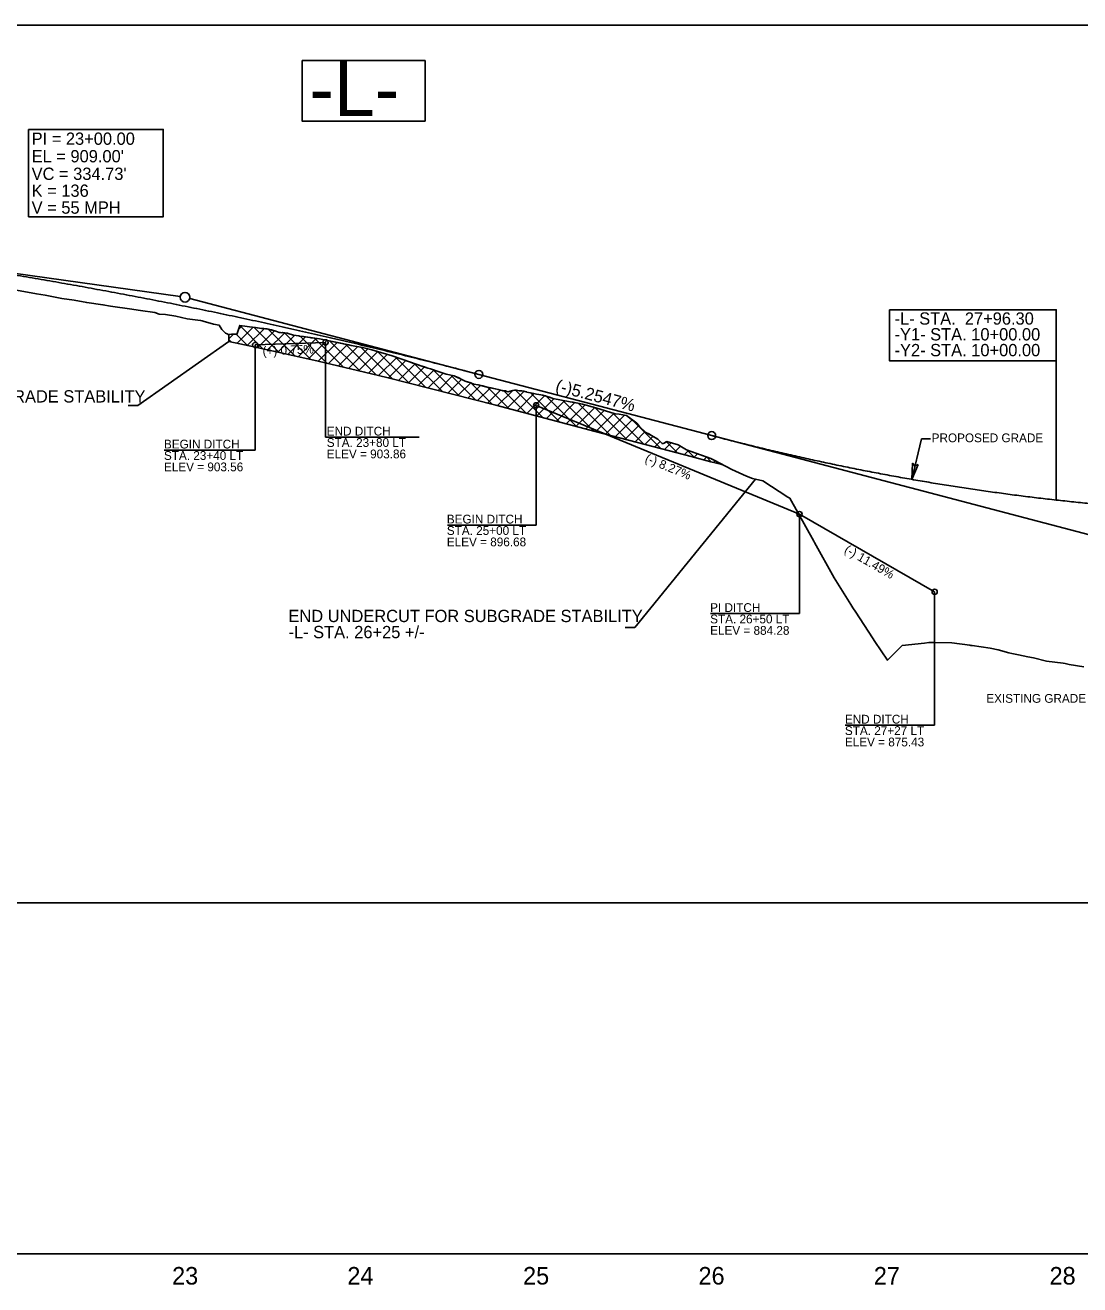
# Model space of a CAD drawing. Extents: x 1968019 to 1983409, y 545058 to 567558.
# Drawn here: x 1970052 to 1970653, y 566291 to 567008 of the extents above; entities that cross this region are included whole.
import ezdxf

# ---------------------------------------------------------------- set-up
doc = ezdxf.new("R2010")
doc.units = 0
for name, color, linetype in [('Exist Profile Cell', 7, 'Continuous'), ('Exist Vertical Profile Ground Line', 7, 'Continuous'), ('Exist Vertical Profile Horizontal Axis Label Major', 7, 'Continuous'), ('Old_Level_1', 7, 'Continuous'), ('Old_Level_20', 7, 'Continuous'), ('Prop Grid Mask', 7, 'Continuous'), ('Prop Road Sect_ Recs - UC (Outline)', 7, 'Continuous'), ('Prop Road Sect_ Recs - UC (pattern)', 7, 'Continuous'), ('Prop Road Sect_ Recs - UC (Tx)', 7, 'Continuous'), ('Prop Terminator CELL', 7, 'Continuous'), ('Prop Vertical Profile Curve Label', 7, 'Continuous'), ('Prop Vertical Profile Ditch Grade Left', 7, 'Continuous'), ('Prop Vertical Profile Ditch Grade Left Label', 7, 'Continuous'), ('Prop Vertical Profile Grade', 7, 'Continuous'), ('Prop Vertical Profile Grade Label', 7, 'Continuous'), ('Prop VPI Label', 7, 'Continuous'), ('Scratch_Level_8', 7, 'Continuous')]:
    doc.layers.add(name, color=color, linetype=linetype)

msp = doc.modelspace()

# ---------------------------------------------------------------- linework, layer by layer
at = {"layer": 'Exist Profile Cell'}
msp.add_line((1968842.96, 566308.43), (1972642.96, 566308.43), dxfattribs=at)
at = {"layer": 'Exist Vertical Profile Ground Line'}
for points in [[(1970046.9, 566857.43), (1970058.36, 566855.38), (1970063.18, 566854.53), (1970072.77, 566852.8), (1970079.73, 566851.7), (1970086.95, 566850.42), (1970096.18, 566849.11), (1970100.53, 566848.37), (1970112.62, 566846.7), (1970113.69, 566846.54), (1970117.65, 566845.93), (1970125.69, 566844.69), (1970128.13, 566843.71), (1970131.76, 566843.64), (1970137.63, 566842.69), (1970144.06, 566841.16), (1970151.84, 566840.25), (1970152.78, 566840.08), (1970153.3, 566839.86), (1970159.08, 566838.12), (1970162.41, 566837.49), (1970163.95, 566835.12), (1970164.65, 566834.38), (1970166.04, 566833.03), (1970166.87, 566832.66), (1970167.53, 566832.27), (1970171.21, 566832.36), (1970172.52, 566832.27), (1970174.12, 566837.33), (1970174.13, 566837.37), (1970185.3, 566835.84), (1970187.86, 566835.53), (1970189.6, 566835.48), (1970194.66, 566834.12), (1970196.65, 566833.37), (1970198.02, 566833.19), (1970198.42, 566833.4), (1970201.17, 566832.99), (1970201.64, 566832.83), (1970204.15, 566831.96), (1970204.71, 566831.8), (1970207.79, 566831.44), (1970208.23, 566831.31), (1970210.51, 566831.01), (1970212.78, 566830.77), (1970214.14, 566830.51), (1970215.57, 566830.25), (1970219.47, 566829.65), (1970229.77, 566827.58), (1970236.26, 566826.27), (1970237.6, 566826), (1970243.97, 566824.79), (1970249.35, 566823.5), (1970253.08, 566822.39), (1970260.86, 566820.11), (1970271.32, 566816.46), (1970274.12, 566815.41), (1970277.28, 566814.44), (1970281.29, 566813.08), (1970282.72, 566812.6), (1970288.2, 566810.69), (1970289.37, 566810.36), (1970291.79, 566809.57), (1970296.28, 566808.61), (1970296.71, 566808.55), (1970301.07, 566806.44), (1970302.56, 566805.58), (1970305.83, 566804.69), (1970307.55, 566803.99), (1970309.96, 566803.52), (1970315.04, 566802.28), (1970319.7, 566801.25), (1970321.41, 566800.86), (1970323.6, 566800.28), (1970323.77, 566800.23), (1970324.05, 566800.14), (1970325.58, 566800.02), (1970326.18, 566799.68), (1970326.88, 566799.51)], [(1970326.88, 566799.51), (1970329.59, 566800.38), (1970331.65, 566800.5), (1970333.31, 566800.12), (1970334.66, 566800.19), (1970337.27, 566799.59), (1970337.47, 566799.52), (1970337.74, 566799.4), (1970341.66, 566798.56), (1970343.1, 566798.3), (1970345.68, 566797.82), (1970347.88, 566797.32), (1970348.27, 566797.23), (1970349.12, 566796.92), (1970351.09, 566796.27), (1970352.45, 566795.72), (1970362.26, 566793.91), (1970365.69, 566793.27), (1970365.81, 566793.25), (1970369.37, 566792.54), (1970376.97, 566790.49), (1970387.99, 566786.97), (1970390.26, 566786.73), (1970394.45, 566786.1), (1970400.22, 566781.6), (1970401.8, 566779.88), (1970405.53, 566776.45), (1970408.7, 566774.59), (1970412.31, 566772.63), (1970412.55, 566772.33), (1970414.74, 566770.02), (1970415.91, 566770.34), (1970417.34, 566771.21), (1970423.89, 566769.35), (1970428.64, 566766.55), (1970442.39, 566761.55), (1970444.39, 566760.56), (1970454.4, 566755.25), (1970462.71, 566751.47), (1970466.27, 566750.2), (1970472.15, 566748.85), (1970486.34, 566739.57), (1970487.46, 566738.88), (1970501.06, 566714.46), (1970501.19, 566714.24), (1970501.34, 566713.99), (1970501.5, 566713.68), (1970512.71, 566693.49), (1970522.19, 566678.39), (1970523.42, 566676.57), (1970525.06, 566674.05), (1970534.5, 566659.39), (1970535.81, 566657.28), (1970543.12, 566646.63), (1970548.01, 566651.56), (1970551.51, 566655.11), (1970564.12, 566656.39), (1970566.66, 566656.7), (1970567.49, 566656.81), (1970568.76, 566656.82), (1970570.35, 566656.76), (1970579.75, 566656.5), (1970590.09, 566655.12), (1970590.66, 566655.05), (1970591.42, 566654.96), (1970601.52, 566653.41), (1970606.18, 566652.49), (1970612.31, 566650.89), (1970613.86, 566650.5), (1970617.81, 566649.69), (1970623.05, 566648.54), (1970626.3, 566647.91), (1970633.73, 566646.1), (1970643.1, 566644.87), (1970644.36, 566644.69), (1970646.66, 566644.27), (1970654.94, 566642.83)]]:
    msp.add_lwpolyline(points, dxfattribs=at)
at = {"layer": 'Old_Level_20'}
for q in [(1970556.88, 566749.68), (1970567.63, 566772.83)]:
    msp.add_line((1970562.46, 566772.83), q, dxfattribs=at)
at = {"layer": 'Prop Grid Mask'}
msp.add_line((1970639.26, 566737.88), (1970639.26, 566817.24), dxfattribs=at)
for points in [[(1970209.57, 566988.31), (1970279.71, 566988.31), (1970279.71, 566953.75), (1970209.57, 566953.75)], [(1970053.84, 566949.03), (1970130.54, 566949.03), (1970130.54, 566899.27), (1970053.84, 566899.27)], [(1970544.18, 566846.26), (1970639.26, 566846.26), (1970639.26, 566817.24), (1970544.18, 566817.24)]]:
    msp.add_lwpolyline(points, close=True, dxfattribs=at)
at = {"layer": 'Prop Road Sect_ Recs - UC (Outline)'}
msp.add_lwpolyline([(1970167.96, 566828.14), (1970183.17, 566824.9), (1970218.74, 566816.98), (1970245.19, 566810.79), (1970257.89, 566807.73), (1970319.96, 566791.92), (1970376.64, 566777.03), (1970414.52, 566767.08), (1970431.3, 566762.67), (1970442.4, 566759.75), (1970448.13, 566758.27), (1970449.27, 566757.97), (1970444.39, 566760.56), (1970443.39, 566761.05), (1970442.39, 566761.55), (1970435.51, 566764.05), (1970428.64, 566766.55), (1970423.89, 566769.35), (1970420.61, 566770.28), (1970417.34, 566771.21), (1970416.62, 566770.77), (1970415.91, 566770.34), (1970415.32, 566770.18), (1970414.74, 566770.02), (1970413.64, 566771.18), (1970412.55, 566772.33), (1970412.31, 566772.63), (1970410.5, 566773.61), (1970408.7, 566774.59), (1970407.11, 566775.52), (1970405.53, 566776.45), (1970401.8, 566779.88), (1970400.22, 566781.6), (1970397.33, 566783.85), (1970394.45, 566786.1), (1970390.26, 566786.73), (1970387.99, 566786.97), (1970376.97, 566790.49), (1970369.37, 566792.54), (1970367.59, 566792.89), (1970365.69, 566793.27), (1970363.97, 566793.59), (1970362.26, 566793.91), (1970357.35, 566794.82), (1970352.45, 566795.72), (1970351.09, 566796.27), (1970348.69, 566797.07), (1970348.27, 566797.23), (1970347.88, 566797.32), (1970346.78, 566797.57), (1970345.68, 566797.82), (1970344.39, 566798.06), (1970343.1, 566798.3), (1970341.66, 566798.56), (1970339.7, 566798.98), (1970337.74, 566799.4), (1970337.6, 566799.46), (1970337.47, 566799.52), (1970337.37, 566799.55), (1970337.27, 566799.59), (1970335.96, 566799.89), (1970334.66, 566800.19), (1970333.31, 566800.12), (1970332.48, 566800.31), (1970331.65, 566800.5), (1970330.62, 566800.44), (1970329.59, 566800.38), (1970328.23, 566799.95), (1970326.88, 566799.51), (1970326.18, 566799.68), (1970325.88, 566799.85), (1970325.58, 566800.02), (1970324.81, 566800.08), (1970324.05, 566800.14), (1970323.91, 566800.19), (1970323.68, 566800.25), (1970322.5, 566800.57), (1970321.41, 566800.86), (1970319.7, 566801.25), (1970317.37, 566801.77), (1970315.04, 566802.28), (1970312.5, 566802.9), (1970309.96, 566803.52), (1970307.55, 566803.99), (1970305.83, 566804.69), (1970304.19, 566805.14), (1970302.56, 566805.58), (1970301.07, 566806.44), (1970298.89, 566807.49), (1970296.71, 566808.55), (1970296.49, 566808.58), (1970296.28, 566808.61), (1970291.79, 566809.57), (1970290.58, 566809.97), (1970289.37, 566810.36), (1970288.2, 566810.69), (1970285.46, 566811.65), (1970282.72, 566812.6), (1970281.29, 566813.08), (1970279.28, 566813.76), (1970277.28, 566814.44), (1970275.7, 566814.92), (1970274.12, 566815.41), (1970272.72, 566815.93), (1970271.32, 566816.46), (1970260.86, 566820.11), (1970249.35, 566823.5), (1970243.97, 566824.79), (1970240.78, 566825.4), (1970237.6, 566826), (1970219.47, 566829.65), (1970217.52, 566829.95), (1970215.57, 566830.25), (1970214.85, 566830.38), (1970214.14, 566830.51), (1970212.78, 566830.77), (1970211.64, 566830.89), (1970210.51, 566831.01), (1970208.23, 566831.31), (1970207.79, 566831.44), (1970206.25, 566831.62), (1970204.71, 566831.8), (1970204.43, 566831.88), (1970204.15, 566831.96), (1970202.89, 566832.4), (1970201.64, 566832.83), (1970201.4, 566832.91), (1970201.17, 566832.99), (1970198.42, 566833.4), (1970198.02, 566833.19), (1970197.33, 566833.28), (1970196.65, 566833.37), (1970195.65, 566833.74), (1970194.66, 566834.12), (1970192.13, 566834.8), (1970189.6, 566835.48), (1970188.73, 566835.5), (1970187.86, 566835.53), (1970186.58, 566835.68), (1970185.3, 566835.84), (1970183.17, 566836.13), (1970179.71, 566836.6), (1970174.13, 566837.37), (1970172.52, 566832.27), (1970171.86, 566832.31), (1970171.21, 566832.36), (1970169.37, 566832.31), (1970167.96, 566832.28)], close=True, dxfattribs=at)
at = {"layer": 'Prop Road Sect_ Recs - UC (pattern)'}
for p, q in [((1970173.42, 566835.14), (1970175.47, 566837.18)), ((1970174.12, 566837.34), (1970187.53, 566823.93)), ((1970167.96, 566829.67), (1970170.63, 566832.34)), ((1970172.09, 566832.3), (1970178.49, 566825.9)), ((1970172.52, 566827.17), (1970181.69, 566836.33)), ((1970178.35, 566825.92), (1970187.95, 566835.52)), ((1970182.27, 566836.25), (1970196.62, 566821.9)), ((1970184.17, 566824.67), (1970193.84, 566834.34)), ((1970189.96, 566823.39), (1970199.77, 566833.2)), ((1970190.3, 566835.29), (1970205.72, 566819.88)), ((1970195.74, 566822.1), (1970205.36, 566831.72)), ((1970199.42, 566833.25), (1970214.81, 566817.85)), ((1970201.52, 566820.81), (1970211.6, 566830.89)), ((1970207.31, 566819.52), (1970217.7, 566829.92)), ((1970208.46, 566831.28), (1970223.99, 566815.75)), ((1970216.74, 566830.07), (1970233.22, 566813.59)), ((1970167.96, 566829.35), (1970169.5, 566827.81)), ((1970213.09, 566818.24), (1970223.66, 566828.8)), ((1970218.87, 566816.95), (1970229.55, 566827.62)), ((1970224.6, 566815.61), (1970235.43, 566826.44)), ((1970225.43, 566828.45), (1970242.45, 566811.43)), ((1970230.33, 566814.27), (1970241.35, 566825.29)), ((1970234.28, 566826.67), (1970251.74, 566809.21)), ((1970236.06, 566812.92), (1970247.16, 566824.03)), ((1970241.79, 566811.58), (1970252.72, 566822.51)), ((1970243.06, 566824.96), (1970261.12, 566806.9)), ((1970252.52, 566822.57), (1970270.6, 566804.49)), ((1970247.51, 566810.23), (1970258.18, 566820.9)), ((1970253.21, 566808.85), (1970263.53, 566819.18)), ((1970258.89, 566807.47), (1970268.77, 566817.35)), ((1970262.69, 566819.47), (1970280.09, 566802.07)), ((1970264.53, 566806.04), (1970273.96, 566815.47)), ((1970273.65, 566815.58), (1970289.58, 566799.66)), ((1970270.16, 566804.6), (1970279.31, 566813.75)), ((1970275.8, 566803.17), (1970284.58, 566811.95)), ((1970281.44, 566801.73), (1970289.9, 566810.19)), ((1970284.24, 566812.07), (1970299.06, 566797.24)), ((1970287.07, 566800.3), (1970295.54, 566808.77)), ((1970294.36, 566809.02), (1970308.55, 566794.83)), ((1970292.71, 566798.86), (1970300.54, 566806.69)), ((1970298.34, 566797.42), (1970305.66, 566804.74)), ((1970303.98, 566795.99), (1970311.21, 566803.22)), ((1970305.73, 566804.72), (1970318.04, 566792.41)), ((1970309.62, 566794.55), (1970316.93, 566801.86)), ((1970315.29, 566802.23), (1970327.61, 566789.91)), ((1970315.25, 566793.12), (1970322.66, 566800.52)), ((1970320.88, 566791.68), (1970329.58, 566800.38)), ((1970324.48, 566800.11), (1970337.2, 566787.39)), ((1970326.48, 566790.21), (1970336.12, 566799.85)), ((1970331.19, 566800.47), (1970346.79, 566784.87)), ((1970332.08, 566788.74), (1970341.87, 566798.52)), ((1970337.68, 566787.27), (1970347.76, 566797.34)), ((1970339.77, 566798.96), (1970356.38, 566782.35)), ((1970343.28, 566785.79), (1970353.09, 566795.6)), ((1970348.75, 566797.06), (1970365.97, 566779.83)), ((1970348.88, 566784.32), (1970359.06, 566794.5)), ((1970358.22, 566794.66), (1970375.56, 566777.31)), ((1970354.48, 566782.85), (1970365.02, 566793.39)), ((1970360.08, 566781.38), (1970370.84, 566792.14)), ((1970365.68, 566779.91), (1970376.41, 566790.64)), ((1970366.92, 566793.02), (1970385.15, 566774.79)), ((1970371.28, 566778.44), (1970381.79, 566788.95)), ((1970376.36, 566790.66), (1970394.74, 566772.27)), ((1970376.88, 566776.97), (1970387.15, 566787.24)), ((1970386.71, 566787.38), (1970404.33, 566769.75)), ((1970382.48, 566775.5), (1970393.27, 566786.28)), ((1970388.08, 566774.02), (1970397.65, 566783.6)), ((1970393.68, 566772.55), (1970401.42, 566780.29)), ((1970397.23, 566783.93), (1970413.92, 566767.23)), ((1970399.28, 566771.08), (1970405.07, 566776.87)), ((1970404.88, 566769.61), (1970409.45, 566774.18)), ((1970410.48, 566768.14), (1970413.58, 566771.24)), ((1970416.08, 566766.67), (1970419.89, 566770.48)), ((1970417.14, 566771.09), (1970423.52, 566764.71)), ((1970421.68, 566765.2), (1970425.11, 566768.63)), ((1970427.28, 566763.72), (1970429.71, 566766.16)), ((1970428.81, 566766.49), (1970433.11, 566762.19)), ((1970432.88, 566762.25), (1970434.9, 566764.27)), ((1970438.48, 566760.78), (1970440.08, 566762.39)), ((1970439.93, 566762.44), (1970442.7, 566759.68)), ((1970444.08, 566759.32), (1970445, 566760.23))]:
    msp.add_line(p, q, dxfattribs=at)
at = {"layer": 'Prop Road Sect_ Recs - UC (Tx)'}
for p, q in [((1970116.05, 566791.73), (1970167.96, 566828.14)), ((1970116.05, 566791.73), (1970110.55, 566791.73)), ((1970467.96, 566749.81), (1970399.22, 566665.18)), ((1970399.22, 566665.18), (1970393.72, 566665.18))]:
    msp.add_line(p, q, dxfattribs=at)
at = {"layer": 'Prop Terminator CELL'}
msp.add_lwpolyline([(1970560.49, 566758.06), (1970556.88, 566749.68), (1970557.44, 566758.85), (1970558.73, 566757.36)], close=True, dxfattribs=at)
at = {"layer": 'Prop Vertical Profile Curve Label'}
for centre in [(1970310.32, 566809.45), (1970442.96, 566774.61)]:
    msp.add_circle(centre, 2.25, dxfattribs=at)
at = {"layer": 'Prop Vertical Profile Ditch Grade Left'}
msp.add_line((1970182.96, 566826.23), (1970222.96, 566827.73), dxfattribs=at)
msp.add_lwpolyline([(1970342.96, 566791.83), (1970492.96, 566729.83), (1970569.96, 566685.58)], dxfattribs=at)
at = {"layer": 'Prop Vertical Profile Ditch Grade Left Label'}
for p, q in [((1970182.96, 566826.23), (1970182.96, 566766.34)), ((1970222.96, 566827.73), (1970222.96, 566773.73)), ((1970342.96, 566791.83), (1970342.96, 566723.61)), ((1970276.34, 566773.73), (1970222.96, 566773.73)), ((1970182.96, 566766.34), (1970131.12, 566766.34)), ((1970492.96, 566729.83), (1970492.96, 566673.2)), ((1970342.96, 566723.61), (1970292.43, 566723.61)), ((1970569.96, 566609.58), (1970569.96, 566685.58)), ((1970492.96, 566673.2), (1970442.35, 566673.2)), ((1970519.03, 566609.58), (1970569.96, 566609.58))]:
    msp.add_line(p, q, dxfattribs=at)
for centre in [(1970182.96, 566826.23), (1970222.96, 566827.73), (1970342.96, 566791.83), (1970492.96, 566729.83), (1970569.96, 566685.58)]:
    msp.add_circle(centre, 1.5, dxfattribs=at)
at = {"layer": 'Prop Vertical Profile Grade'}
msp.add_line((1970310.32, 566809.45), (1970442.96, 566774.61), dxfattribs=at)
for points in [[(1969975.59, 566876.85), (1969982.29, 566875.91), (1969988.98, 566874.95), (1969995.68, 566873.97), (1970002.37, 566872.97), (1970009.07, 566871.96), (1970015.76, 566870.94), (1970022.45, 566869.89), (1970029.15, 566868.83), (1970035.84, 566867.76), (1970042.54, 566866.66), (1970049.23, 566865.55), (1970055.93, 566864.43), (1970062.62, 566863.28), (1970069.32, 566862.12), (1970076.01, 566860.95), (1970082.71, 566859.76), (1970089.4, 566858.55), (1970096.09, 566857.32), (1970102.79, 566856.08), (1970109.48, 566854.83), (1970116.18, 566853.55), (1970122.87, 566852.26), (1970129.57, 566850.95), (1970136.26, 566849.63), (1970142.96, 566848.29), (1970149.65, 566846.93), (1970156.35, 566845.56), (1970163.04, 566844.17), (1970169.73, 566842.77), (1970176.43, 566841.35), (1970183.12, 566839.91), (1970189.82, 566838.45), (1970196.51, 566836.98), (1970203.21, 566835.49), (1970209.9, 566833.99), (1970216.6, 566832.47), (1970223.29, 566830.93), (1970229.98, 566829.38), (1970236.68, 566827.81), (1970243.37, 566826.22), (1970250.07, 566824.62), (1970256.76, 566823), (1970263.46, 566821.36), (1970270.15, 566819.71), (1970276.85, 566818.04), (1970283.54, 566816.36), (1970290.24, 566814.66), (1970296.93, 566812.94), (1970303.62, 566811.21), (1970310.32, 566809.45)], [(1970442.96, 566774.61), (1970452.96, 566772.02), (1970462.96, 566769.51), (1970472.96, 566767.07), (1970482.96, 566764.71), (1970492.96, 566762.43), (1970502.96, 566760.23), (1970512.96, 566758.1), (1970522.96, 566756.05), (1970532.96, 566754.08), (1970542.96, 566752.19), (1970552.96, 566750.37), (1970562.96, 566748.63), (1970572.96, 566746.96), (1970582.96, 566745.38), (1970592.96, 566743.87), (1970602.96, 566742.44), (1970612.96, 566741.08), (1970622.96, 566739.8), (1970632.96, 566738.6), (1970642.96, 566737.48), (1970652.96, 566736.43), (1970662.96, 566735.46), (1970672.96, 566734.57), (1970682.96, 566733.75), (1970692.96, 566733.01), (1970702.96, 566732.35), (1970712.96, 566731.77), (1970722.96, 566731.26), (1970732.96, 566730.83), (1970742.96, 566730.47), (1970752.96, 566730.2), (1970762.96, 566730), (1970772.96, 566729.88), (1970782.96, 566729.83), (1970792.96, 566729.86), (1970802.96, 566729.97), (1970812.96, 566730.16), (1970822.96, 566730.42), (1970832.96, 566730.76), (1970842.96, 566731.18), (1970852.96, 566731.68), (1970862.96, 566732.25), (1970872.96, 566732.9), (1970882.96, 566733.62), (1970892.96, 566734.43), (1970902.96, 566735.31), (1970912.96, 566736.26), (1970922.96, 566737.3), (1970932.96, 566738.41), (1970942.96, 566739.6)]]:
    msp.add_spline(points, degree=3, dxfattribs=at)
at = {"layer": 'Prop VPI Label'}
for p, q in [((1969975.59, 566876.85), (1970140.23, 566853.81)), ((1970310.32, 566809.45), (1970145.62, 566852.73)), ((1970442.96, 566774.61), (1970690.3, 566709.62))]:
    msp.add_line(p, q, dxfattribs=at)
msp.add_circle((1970142.96, 566853.43), 2.75, dxfattribs=at)
at = {"layer": 'Scratch_Level_8'}
msp.add_lwpolyline([(1969542.96, 566508.43), (1970942.96, 566508.43), (1970942.96, 566812.08), (1970792.94, 566812.08), (1970792.94, 567008.42), (1969542.96, 567008.43)], close=True, dxfattribs=at)

# ---------------------------------------------------------------- texts
at = {"layer": 'Exist Vertical Profile Horizontal Axis Label Major'}
for s, p in [('23', (1970135.57, 566290.93)), ('24', (1970235.41, 566290.93)), ('25', (1970335.5, 566290.93)), ('26', (1970435.44, 566290.93)), ('27', (1970535.3, 566290.93)), ('28', (1970635.42, 566290.93))]:
    msp.add_text(s, height=10, dxfattribs=at).set_placement(p)
at = {"layer": 'Old_Level_1'}
msp.add_text('-L-', height=31.25, dxfattribs=at).set_placement((1970213.88, 566956.72))
at = {"layer": 'Old_Level_20'}
for s, p in [('PROPOSED GRADE', (1970568.27, 566770.83)), ('EXISTING GRADE', (1970599.37, 566622.39))]:
    msp.add_text(s, height=5, rotation=360, dxfattribs=at).set_placement(p)
at = {"layer": 'Prop Road Sect_ Recs - UC (Tx)'}
for s, p in [('BEGIN UNDERCUT FOR SUBGRADE STABILITY', (1969909.26, 566793.46)), ('END UNDERCUT FOR SUBGRADE STABILITY', (1970201.87, 566668.35)), ('-L- STA. 26+25 +/-', (1970201.87, 566659.18))]:
    msp.add_text(s, height=7, dxfattribs=at).set_placement(p)
at = {"layer": 'Prop Vertical Profile Curve Label'}
for s, p in [("VC = 334.73'", (1970055.55, 566920.28)), ('K = 136', (1970055.55, 566910.65)), ('V = 55 MPH', (1970055.55, 566901.02))]:
    msp.add_text(s, height=7, dxfattribs=at).set_placement(p)
at = {"layer": 'Prop Vertical Profile Ditch Grade Left Label'}
for s, rotation, p in [('(+) 0.75%', 2.14759, (1970187.21, 566820.32)), ('(-) 8.27%', 337.54306, (1970404.54, 566759.8)), ('(-) 11.49%', 330.11508, (1970518.06, 566708.27))]:
    msp.add_text(s, height=5, rotation=rotation, dxfattribs=at).set_placement(p)
for s, p in [('END DITCH', (1970223.67, 566774.65)), ('BEGIN DITCH', (1970130.93, 566767.26)), ('STA. 23+80 LT', (1970223.67, 566768.15)), ('STA. 23+40 LT', (1970130.93, 566760.76)), ('ELEV = 903.86', (1970223.67, 566761.65)), ('ELEV = 903.56', (1970130.93, 566754.26)), ('BEGIN DITCH', (1970292.08, 566724.53)), ('STA. 25+00 LT', (1970292.08, 566718.03)), ('ELEV = 896.68', (1970292.08, 566711.53)), ('PI DITCH', (1970442.08, 566674.12)), ('STA. 26+50 LT', (1970442.08, 566667.62)), ('ELEV = 884.28', (1970442.08, 566661.12)), ('END DITCH', (1970518.83, 566610.53)), ('STA. 27+27 LT', (1970518.83, 566604.03)), ('ELEV = 875.43', (1970518.83, 566597.53))]:
    msp.add_text(s, height=5, dxfattribs=at).set_placement(p)
at = {"layer": 'Prop Vertical Profile Grade Label'}
msp.add_text('(-)5.2547%', height=7, rotation=345.27913, dxfattribs=at).set_placement((1970353.52, 566799.95))
at = {"layer": 'Prop VPI Label'}
for s, p in [('PI = 23+00.00', (1970055.55, 566940.28)), ("EL = 909.00'", (1970055.55, 566930.28)), ('-L- STA.  27+96.30', (1970547.12, 566837.82)), ('-Y1- STA. 10+00.00', (1970547.12, 566828.82)), ('-Y2- STA. 10+00.00', (1970547.12, 566819.82))]:
    msp.add_text(s, height=7, dxfattribs=at).set_placement(p)

doc.saveas('drawing.dxf')
